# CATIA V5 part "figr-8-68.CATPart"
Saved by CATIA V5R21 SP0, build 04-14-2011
Part number: Part1
Bounding box of the stored display mesh (mm): x -84.762 to 84.762, y -75 to 75, z 0 to 50
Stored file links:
  D:\CATIA V5R21 E-RESOURCES\CATIA-V5R21\catia-v5r21-prt\c08-catia-v5r20-prt\c08-catia-v5r21-figr-8-68.CATPart
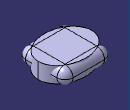
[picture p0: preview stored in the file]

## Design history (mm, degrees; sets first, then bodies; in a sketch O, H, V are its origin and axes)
Body1 (main body)
  Sketch1 on xy-plane, origin (0, 0, 0), H (1, 0, 0), V (0, 1, 0)
    line L1 (-75, 75) -> (75, 75)
    line L2 (75, 75) -> (75, -75)
    line L3 (75, -75) -> (-75, -75)
    line L4 (-75, -75) -> (-75, 75)
    axis line L5 (75, -75) -> (-75, 75)
    length L3 = 150
    length L2 = 150
    horizontal: L1 H, L3 H
    vertical: L2 V, L4 V
    midpoint: O L5
  Pad1: profile Sketch1, direction (0, 0, 1), length 50
  Fillet1: radius 25, on face of Pad1 (x6)
Body2
  Sketch2 on xy-plane, origin (0, 0, 0), H (1, 0, 0), V (0, 1, 0)
    ellipse A1 centre (0, 0) semi-axes 84.7617, 65.8627 rotation 0
    point P1 (84.7617, 0)
    point P2 (0, 65.8627)
    coincidence: P1 H, P2 V, A1 P1, A1 P2
  Pad2: profile Sketch2, direction (0, 0, 1), length 50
